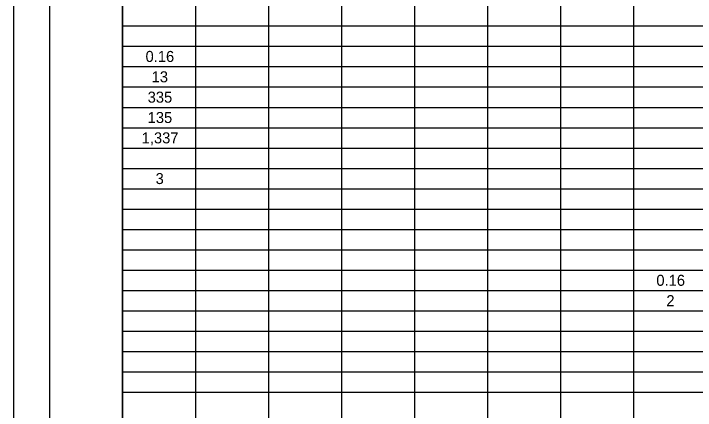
# Model space of a CAD drawing. Extents: x 0 to 34, y 0 to 22.
# Drawn here: x 0 to 9.39, y 10.89 to 16.35 of the extents above; entities that cross this region are included whole.
import ezdxf

# ---------------------------------------------------------------- set-up
doc = ezdxf.new("R2010")
doc.units = 0
for name, color, linetype in [('Default', 7, 'Continuous'), ('SH_Border', 7, 'Continuous'), ('SH_Cut_Line', 7, 'Continuous')]:
    doc.layers.add(name, color=color, linetype=linetype)

msp = doc.modelspace()

# ---------------------------------------------------------------- linework, layer by layer
at = {"layer": 'Default'}
for p, q in [((1.5, 21.5), (1.5, 0.5024)), ((2.5046, 20.9401), (2.5046, 0.5024)), ((3.5092, 20.9401), (3.5092, 0.5024)), ((4.5138, 20.9401), (4.5138, 0.5024)), ((5.5184, 20.9401), (5.5184, 0.5024)), ((6.5229, 20.9401), (6.5229, 0.5024)), ((7.5275, 20.9401), (7.5275, 0.5024)), ((8.5321, 20.9401), (8.5321, 0.5024)), ((1.5, 16.1806), (32, 16.1806)), ((1.5, 15.9006), (32, 15.9006)), ((1.5, 15.6207), (32, 15.6207)), ((1.5, 15.3407), (32, 15.3407)), ((1.5, 15.0607), (32, 15.0607)), ((1.5, 14.7808), (32, 14.7808)), ((1.5, 14.5008), (32, 14.5008)), ((1.5, 14.2208), (32, 14.2208)), ((1.5, 13.9409), (32, 13.9409)), ((1.5, 13.6609), (32, 13.6609)), ((1.5, 13.3809), (32, 13.3809)), ((1.5, 13.101), (32, 13.101)), ((1.5, 12.821), (32, 12.821)), ((1.5, 12.541), (32, 12.541)), ((1.5, 12.2611), (32, 12.2611)), ((1.5, 11.9811), (32, 11.9811)), ((1.5, 11.7011), (32, 11.7011)), ((1.5, 11.4212), (32, 11.4212)), ((1.5, 11.1412), (32, 11.1412))]:
    msp.add_line(p, q, dxfattribs=at)
at = {"layer": 'SH_Border'}
for points in [[(0.5, 21.5), (1.5, 21.5), (1.5, 0.5), (0.5, 0.5)], [(1.5, 21.5), (33.5, 21.5), (33.5, 0.5), (1.5, 0.5)]]:
    msp.add_lwpolyline(points, close=True, dxfattribs=at)
at = {"layer": 'SH_Cut_Line'}
msp.add_lwpolyline([(0, 0), (34, 0), (34, 22), (0, 22)], close=True, dxfattribs=at)

# ---------------------------------------------------------------- texts
at = {"layer": 'Default'}
for s, height, p in [('0.16', 0.15151, (1.8161, 15.6849)), ('13', 0.15151, (1.9, 15.4049)), ('335', 0.15151, (1.8453, 15.125)), ('135', 0.15151, (1.8453, 14.845)), ('1,337', 0.15151, (1.7627, 14.565)), ('3', 0.1515, (1.9544, 14.0051)), ('0.16', 0.15151, (8.8483, 12.6053)), ('2', 0.1515, (8.986, 12.3253))]:
    msp.add_text(s, height=height, dxfattribs=at).set_placement(p)

doc.saveas('drawing.dxf')
